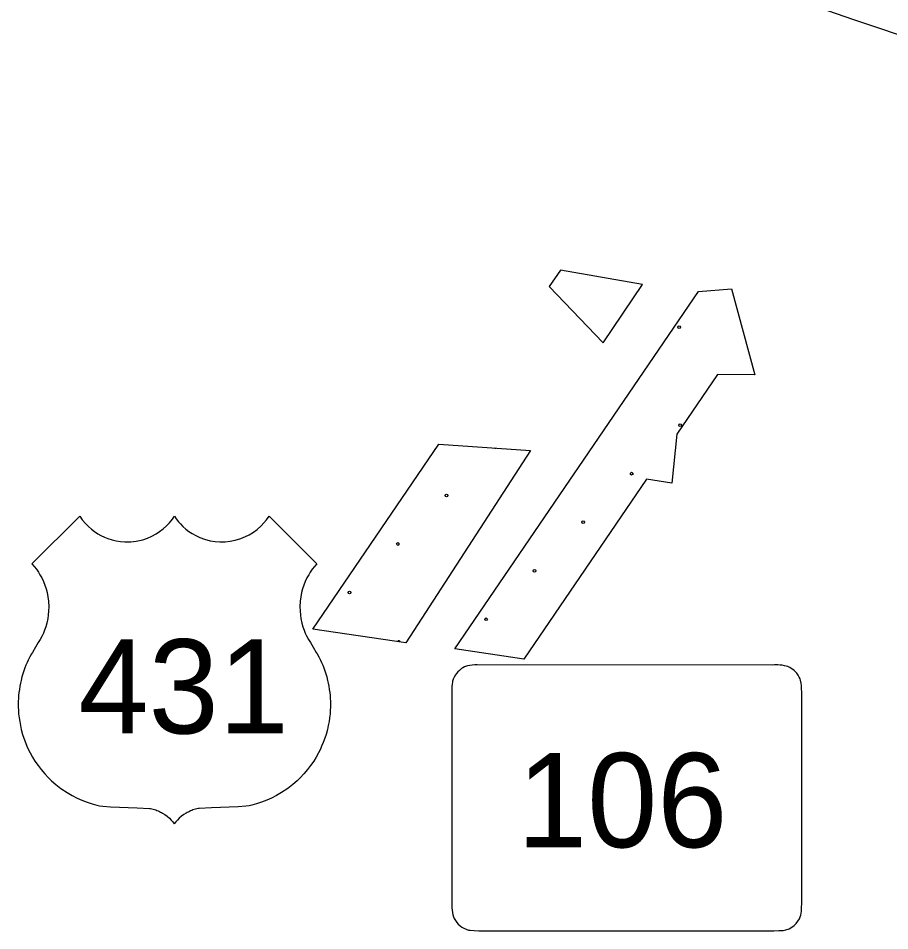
# Model space of a CAD drawing. Extents: x 1612280 to 1883141, y 560852 to 780851.
# Drawn here: x 1710296 to 1713714, y 621879 to 625458 of the extents above; entities that cross this region are included whole.
import ezdxf

# ---------------------------------------------------------------- set-up
doc = ezdxf.new("R2010")
doc.units = 0
for name, color, linetype in [('DESIGN - EROSION CONTROL - Devices', 7, 'Continuous'), ('DESIGN - ROW - Slope Lines', 7, 'Continuous'), ('DESIGN - SCRATCH - User 1', 7, 'Continuous'), ('SURVEY - DRAINAGE - Bridge Deck with Text', 7, 'Continuous')]:
    doc.layers.add(name, color=color, linetype=linetype)

msp = doc.modelspace()

# ---------------------------------------------------------------- linework, layer by layer
at = {"layer": 'DESIGN - EROSION CONTROL - Devices'}
for centre in [(1712888.8, 624246.8), (1712888.8, 624246.8), (1712892.5, 623862.2), (1712892.5, 623862.2), (1712702.1, 623671.8), (1712702.1, 623671.8), (1711975.9, 623586.3), (1711975.9, 623586.3), (1712511.7, 623481.4), (1712511.7, 623481.4), (1711785.5, 623395.9), (1711785.5, 623395.9), (1712321.3, 623291), (1712321.3, 623291), (1711595.1, 623205.5), (1711595.1, 623205.5), (1712130.9, 623100.6), (1712130.9, 623100.6)]:
    msp.add_circle(centre, 5.28, dxfattribs=at)
for centre, start, end in [((1712166.3, 623776.7), 226.9306, 305.1717), ((1711789.2, 623011.3), 356.6323, 166.4726)]:
    msp.add_arc(centre, 5.28, start, end, dxfattribs=at)
at = {"layer": 'DESIGN - ROW - Slope Lines'}
msp.add_line((1711996.3, 622820.2), (1711996.3, 621988.4), dxfattribs=at)
msp.add_line((1711996.3, 622820.2), (1711996.3, 621988.4), dxfattribs=at)
for points in [[(1713369.2, 622809.7), (1713369, 622817.5), (1713368.9, 622825.6), (1713367.8, 622840.2), (1713366.5, 622850.6), (1713364.7, 622861.4), (1713362.7, 622867.4), (1713359.5, 622874), (1713355.1, 622881.5), (1713349.7, 622888.9), (1713345, 622894.3), (1713339.1, 622899.9), (1713334.4, 622903.7), (1713328, 622908.2), (1713323, 622911.1), (1713314.6, 622915.1), (1713308.5, 622917.3), (1713301.4, 622918.7), (1713292.1, 622920.1), (1713284, 622920.9), (1713275.3, 622921.4), (1713263, 622921.6), (1713253.5, 622920.9), (1712096.3, 622921.6), (1712086.9, 622921.6), (1712076.6, 622920.9), (1712067.4, 622919.7), (1712058.4, 622918.1), (1712054.1, 622916.8), (1712046.9, 622913.7), (1712040.4, 622910.3), (1712035.2, 622907.1), (1712026.3, 622900.2), (1712020.2, 622894.4), (1712015, 622888.6), (1712011.1, 622883.3), (1712005.4, 622873.7), (1712002, 622866.3), (1712000.1, 622861.2), (1711999.4, 622857.4), (1711998.9, 622854), (1711998, 622846.8), (1711996.9, 622837.5), (1711996.5, 622829.6), (1711996.3, 622822.9), (1711996.3, 622804.9)], [(1713369.2, 622809.7), (1713369, 622817.5), (1713368.9, 622825.6), (1713367.8, 622840.2), (1713366.5, 622850.6), (1713364.7, 622861.4), (1713362.7, 622867.4), (1713359.5, 622874), (1713355.1, 622881.5), (1713349.7, 622888.9), (1713345, 622894.3), (1713339.1, 622899.9), (1713334.4, 622903.7), (1713328, 622908.2), (1713323, 622911.1), (1713314.6, 622915.1), (1713308.5, 622917.3), (1713301.4, 622918.7), (1713292.1, 622920.1), (1713284, 622920.9), (1713275.3, 622921.4), (1713263, 622921.6), (1713253.5, 622920.9), (1712096.3, 622921.6), (1712086.9, 622921.6), (1712076.6, 622920.9), (1712067.4, 622919.7), (1712058.4, 622918.1), (1712054.1, 622916.8), (1712046.9, 622913.7), (1712040.4, 622910.3), (1712035.2, 622907.1), (1712026.3, 622900.2), (1712020.2, 622894.4), (1712015, 622888.6), (1712011.1, 622883.3), (1712005.4, 622873.7), (1712002, 622866.3), (1712000.1, 622861.2), (1711999.4, 622857.4), (1711998.9, 622854), (1711998, 622846.8), (1711996.9, 622837.5), (1711996.5, 622829.6), (1711996.3, 622822.9), (1711996.3, 622804.9)], [(1713259.3, 621879.1), (1713279.9, 621879.4), (1713297, 621879.6), (1713307.2, 621882.1), (1713319.5, 621886.9), (1713330.6, 621893.3), (1713339.6, 621900.1), (1713347.7, 621908.1), (1713353.9, 621916.1), (1713359.9, 621925.9), (1713363.5, 621933.6), (1713366.1, 621940.7), (1713367.6, 621948.2), (1713368.4, 621956.5), (1713368.7, 621966.5), (1713369.2, 621989.8), (1713369.2, 622809.7)], [(1713259.3, 621879.1), (1713279.9, 621879.4), (1713297, 621879.6), (1713307.2, 621882.1), (1713319.5, 621886.9), (1713330.6, 621893.3), (1713339.6, 621900.1), (1713347.7, 621908.1), (1713353.9, 621916.1), (1713359.9, 621925.9), (1713363.5, 621933.6), (1713366.1, 621940.7), (1713367.6, 621948.2), (1713368.4, 621956.5), (1713368.7, 621966.5), (1713369.2, 621989.8), (1713369.2, 622809.7)], [(1711996.3, 621988.4), (1711996.4, 621979.4), (1711997, 621969.2), (1711997.8, 621959.8), (1711998.9, 621950.6), (1712000.3, 621941.3), (1712003, 621933.7), (1712006.5, 621926.5), (1712011, 621919), (1712016.4, 621911.7), (1712022, 621905.5), (1712029.2, 621898.9), (1712036.2, 621893.7), (1712044.2, 621889), (1712052.8, 621885), (1712061.7, 621881.9), (1712069, 621881), (1712083.9, 621879.7), (1712102.7, 621879), (1713259.3, 621879.1)], [(1711996.3, 621988.4), (1711996.4, 621979.4), (1711997, 621969.2), (1711997.8, 621959.8), (1711998.9, 621950.6), (1712000.3, 621941.3), (1712003, 621933.7), (1712006.5, 621926.5), (1712011, 621919), (1712016.4, 621911.7), (1712022, 621905.5), (1712029.2, 621898.9), (1712036.2, 621893.7), (1712044.2, 621889), (1712052.8, 621885), (1712061.7, 621881.9), (1712069, 621881), (1712083.9, 621879.7), (1712102.7, 621879), (1713259.3, 621879.1)]]:
    msp.add_lwpolyline(points, dxfattribs=at)
at = {"layer": 'DESIGN - SCRATCH - User 1'}
for points in [[(1713573.2, 625451.4), (1712973.7, 625661.3), (1712094, 625973.3)], [(1713573.2, 625451.4), (1712973.7, 625661.3), (1712094, 625973.3)], [(1716206.8, 624740.1), (1715273.3, 624946.3), (1714579.1, 625135.7), (1714107.7, 625273.1), (1713573.2, 625451.4)], [(1716206.8, 624740.1), (1715273.3, 624946.3), (1714579.1, 625135.7), (1714107.7, 625273.1), (1713573.2, 625451.4)], [(1712744.9, 624414), (1712422.8, 624469.7), (1712378, 624406.1)], [(1712744.9, 624414), (1712422.8, 624469.7), (1712378, 624406.1)], [(1712590, 624184.5), (1712744.9, 624414)], [(1712590, 624184.5), (1712744.9, 624414)], [(1712008.5, 622984.5), (1712964, 624386.2), (1713093.8, 624396.2)], [(1712008.5, 622984.5), (1712964, 624386.2), (1713093.8, 624396.2)], [(1712378, 624406.1), (1712590, 624184.5)], [(1712378, 624406.1), (1712590, 624184.5)], [(1713093.8, 624396.2), (1713184.9, 624060)], [(1713093.8, 624396.2), (1713184.9, 624060)], [(1713038.6, 624060.6), (1712879.1, 623826.2)], [(1713038.6, 624060.6), (1712879.1, 623826.2)], [(1713184.9, 624060), (1713038.6, 624060.6)], [(1713184.9, 624060), (1713038.6, 624060.6)], [(1712879.1, 623826.2), (1712860, 623635)], [(1712879.1, 623826.2), (1712860, 623635)], [(1711451.8, 623061.9), (1711945.8, 623787.8), (1712305.1, 623763)], [(1711451.8, 623061.9), (1711945.8, 623787.8), (1712305.1, 623763)], [(1712305.1, 623763), (1711816.5, 623007.8)], [(1712305.1, 623763), (1711816.5, 623007.8)], [(1712759.7, 623650.8), (1712279, 622944.3)], [(1712759.7, 623650.8), (1712279, 622944.3)], [(1712860, 623635), (1712759.7, 623650.8)], [(1712860, 623635), (1712759.7, 623650.8)], [(1711816.5, 623007.8), (1711451.8, 623061.9)], [(1711816.5, 623007.8), (1711451.8, 623061.9)], [(1712279, 622944.3), (1712008.5, 622984.5)], [(1712279, 622944.3), (1712008.5, 622984.5)]]:
    msp.add_lwpolyline(points, dxfattribs=at)
at = {"layer": 'SURVEY - DRAINAGE - Bridge Deck with Text'}
for points in [[(1710350, 623318.2), (1710537.5, 623504.6), (1710547.3, 623490.8), (1710559.6, 623476.1), (1710571.6, 623463.9), (1710582.8, 623454.1), (1710595.2, 623444.7), (1710608.1, 623436.3), (1710620.5, 623429.3), (1710635, 623422.3), (1710648.1, 623417.1), (1710664.5, 623412), (1710680.1, 623408.3), (1710696.6, 623405.7), (1710714.3, 623404.3), (1710722.3, 623404.1), (1710730.4, 623404.2), (1710738.3, 623404.6), (1710748.4, 623405.5), (1710758.8, 623407), (1710772.2, 623409.6), (1710784.7, 623412.8), (1710802.9, 623418.9), (1710820.1, 623426.5), (1710836.6, 623435.4), (1710850.5, 623444.4), (1710864.3, 623454.9), (1710877.6, 623466.8), (1710889.6, 623479.5), (1710900.8, 623493.4), (1710908.7, 623504.6), (1710915.5, 623494.7), (1710924.3, 623483.5), (1710932.3, 623474.5), (1710941.5, 623465.1), (1710953.2, 623454.7), (1710965.7, 623445.2), (1710978.8, 623436.6), (1710992.4, 623428.9), (1711008.4, 623421.4), (1711027, 623414.5), (1711048.3, 623408.9), (1711069.1, 623405.5), (1711087.3, 623404.2), (1711107.1, 623404.4), (1711127.3, 623406.5), (1711147.5, 623410.6), (1711169.8, 623417.4), (1711187.5, 623424.7), (1711202.1, 623432.1), (1711219.1, 623442.6), (1711233.3, 623453.2), (1711249.1, 623467.2), (1711259.9, 623478.5), (1711269.7, 623490.4), (1711279.8, 623504.6), (1711466.6, 623318.2)], [(1710350, 623318.2), (1710537.5, 623504.6), (1710547.3, 623490.8), (1710559.6, 623476.1), (1710571.6, 623463.9), (1710582.8, 623454.1), (1710595.2, 623444.7), (1710608.1, 623436.3), (1710620.5, 623429.3), (1710635, 623422.3), (1710648.1, 623417.1), (1710664.5, 623412), (1710680.1, 623408.3), (1710696.6, 623405.7), (1710714.3, 623404.3), (1710722.3, 623404.1), (1710730.4, 623404.2), (1710738.3, 623404.6), (1710748.4, 623405.5), (1710758.8, 623407), (1710772.2, 623409.6), (1710784.7, 623412.8), (1710802.9, 623418.9), (1710820.1, 623426.5), (1710836.6, 623435.4), (1710850.5, 623444.4), (1710864.3, 623454.9), (1710877.6, 623466.8), (1710889.6, 623479.5), (1710900.8, 623493.4), (1710908.7, 623504.6), (1710915.5, 623494.7), (1710924.3, 623483.5), (1710932.3, 623474.5), (1710941.5, 623465.1), (1710953.2, 623454.7), (1710965.7, 623445.2), (1710978.8, 623436.6), (1710992.4, 623428.9), (1711008.4, 623421.4), (1711027, 623414.5), (1711048.3, 623408.9), (1711069.1, 623405.5), (1711087.3, 623404.2), (1711107.1, 623404.4), (1711127.3, 623406.5), (1711147.5, 623410.6), (1711169.8, 623417.4), (1711187.5, 623424.7), (1711202.1, 623432.1), (1711219.1, 623442.6), (1711233.3, 623453.2), (1711249.1, 623467.2), (1711259.9, 623478.5), (1711269.7, 623490.4), (1711279.8, 623504.6), (1711466.6, 623318.2)], [(1710350, 623318.2), (1710359.2, 623307.5), (1710367.4, 623296.8), (1710375, 623285.7), (1710381.3, 623275.4), (1710388.1, 623263), (1710394.6, 623249.1), (1710400.2, 623235), (1710405.4, 623219.6), (1710409.2, 623205.1), (1710412.4, 623189.2), (1710414.6, 623171.4), (1710415.7, 623149.8), (1710415.4, 623133.3), (1710414, 623117.4), (1710411.9, 623103.4), (1710408, 623085.2), (1710404.1, 623071.4), (1710399.6, 623058.2), (1710394.6, 623046.1), (1710389.8, 623035.7), (1710382.1, 623022), (1710374.8, 623009.4), (1710364.4, 622991.8), (1710351.5, 622970.7), (1710347.8, 622964.7), (1710341.9, 622953.7), (1710335.3, 622940.5), (1710331.1, 622931.4), (1710326.3, 622920.1), (1710322.2, 622909.8), (1710318.3, 622898.8), (1710314.5, 622887.1), (1710310.8, 622874.5), (1710307.3, 622861.1), (1710304.8, 622849.9), (1710302.4, 622837.8), (1710300.5, 622825.9), (1710298.8, 622813.2), (1710297.6, 622801.6), (1710296.8, 622790), (1710296.3, 622779.2), (1710296.1, 622768), (1710296.2, 622755.6), (1710296.7, 622744), (1710297.7, 622729.5), (1710299.4, 622714.4), (1710301.7, 622699.1), (1710304.4, 622684.4), (1710308.1, 622668.1), (1710313.4, 622649), (1710318, 622634.4), (1710324.5, 622616.8), (1710330.4, 622603.2), (1710335.5, 622591.6), (1710342.8, 622576.9), (1710352.6, 622559.4), (1710361.7, 622544.7), (1710373.7, 622527.2), (1710386.2, 622510.9), (1710400, 622494.6), (1710414.5, 622479.3), (1710427, 622467.3), (1710443.9, 622452.6), (1710463.6, 622437.2), (1710487.8, 622420.9), (1710508.1, 622409.1), (1710527.5, 622399.2), (1710545.6, 622391.1), (1710566.4, 622383), (1710585.6, 622376.7), (1710605, 622371.4), (1710614.9, 622369.1), (1710627.5, 622367.4), (1710657.6, 622364.8), (1710763.2, 622361.5), (1710810.9, 622359), (1710815.4, 622358.5), (1710820.3, 622357.4), (1710825.4, 622356.1), (1710830.4, 622354.6), (1710835.2, 622353), (1710839.8, 622351.3), (1710845.1, 622349.2), (1710849.5, 622347.2), (1710854.6, 622344.7), (1710858.5, 622342.7), (1710862.5, 622340.4), (1710871.1, 622335), (1710880.2, 622328.3), (1710888.8, 622320.9), (1710896.4, 622313.4), (1710902.8, 622306), (1710908.3, 622297.8)], [(1710350, 623318.2), (1710359.2, 623307.5), (1710367.4, 623296.8), (1710375, 623285.7), (1710381.3, 623275.4), (1710388.1, 623263), (1710394.6, 623249.1), (1710400.2, 623235), (1710405.4, 623219.6), (1710409.2, 623205.1), (1710412.4, 623189.2), (1710414.6, 623171.4), (1710415.7, 623149.8), (1710415.4, 623133.3), (1710414, 623117.4), (1710411.9, 623103.4), (1710408, 623085.2), (1710404.1, 623071.4), (1710399.6, 623058.2), (1710394.6, 623046.1), (1710389.8, 623035.7), (1710382.1, 623022), (1710374.8, 623009.4), (1710364.4, 622991.8), (1710351.5, 622970.7), (1710347.8, 622964.7), (1710341.9, 622953.7), (1710335.3, 622940.5), (1710331.1, 622931.4), (1710326.3, 622920.1), (1710322.2, 622909.8), (1710318.3, 622898.8), (1710314.5, 622887.1), (1710310.8, 622874.5), (1710307.3, 622861.1), (1710304.8, 622849.9), (1710302.4, 622837.8), (1710300.5, 622825.9), (1710298.8, 622813.2), (1710297.6, 622801.6), (1710296.8, 622790), (1710296.3, 622779.2), (1710296.1, 622768), (1710296.2, 622755.6), (1710296.7, 622744), (1710297.7, 622729.5), (1710299.4, 622714.4), (1710301.7, 622699.1), (1710304.4, 622684.4), (1710308.1, 622668.1), (1710313.4, 622649), (1710318, 622634.4), (1710324.5, 622616.8), (1710330.4, 622603.2), (1710335.5, 622591.6), (1710342.8, 622576.9), (1710352.6, 622559.4), (1710361.7, 622544.7), (1710373.7, 622527.2), (1710386.2, 622510.9), (1710400, 622494.6), (1710414.5, 622479.3), (1710427, 622467.3), (1710443.9, 622452.6), (1710463.6, 622437.2), (1710487.8, 622420.9), (1710508.1, 622409.1), (1710527.5, 622399.2), (1710545.6, 622391.1), (1710566.4, 622383), (1710585.6, 622376.7), (1710605, 622371.4), (1710614.9, 622369.1), (1710627.5, 622367.4), (1710657.6, 622364.8), (1710763.2, 622361.5), (1710810.9, 622359), (1710815.4, 622358.5), (1710820.3, 622357.4), (1710825.4, 622356.1), (1710830.4, 622354.6), (1710835.2, 622353), (1710839.8, 622351.3), (1710845.1, 622349.2), (1710849.5, 622347.2), (1710854.6, 622344.7), (1710858.5, 622342.7), (1710862.5, 622340.4), (1710871.1, 622335), (1710880.2, 622328.3), (1710888.8, 622320.9), (1710896.4, 622313.4), (1710902.8, 622306), (1710908.3, 622297.8)], [(1711466.6, 623318.2), (1711457.5, 623307.6), (1711449.3, 623296.9), (1711441.7, 623285.7), (1711435.4, 623275.4), (1711428.5, 623263), (1711422, 623249.1), (1711416.4, 623235), (1711411.3, 623219.6), (1711407.5, 623205.2), (1711404.3, 623189.2), (1711402, 623171.5), (1711400.9, 623149.8), (1711401.3, 623133.4), (1711402.7, 623117.4), (1711404.7, 623103.4), (1711408.7, 623085.2), (1711412.6, 623071.4), (1711417.1, 623058.3), (1711422, 623046.2), (1711426.8, 623035.8), (1711434.6, 623022), (1711441.8, 623009.5), (1711452.3, 622991.8), (1711465.2, 622970.7), (1711468.8, 622964.8), (1711474.8, 622953.7), (1711481.4, 622940.6), (1711485.5, 622931.4), (1711490.3, 622920.1), (1711494.4, 622909.8), (1711498.3, 622898.8), (1711502.2, 622887.1), (1711505.9, 622874.5), (1711509.4, 622861.1), (1711511.9, 622849.9), (1711514.2, 622837.9), (1711516.2, 622825.9), (1711517.9, 622813.2), (1711519.1, 622801.6), (1711519.9, 622790.1), (1711520.4, 622779.2), (1711520.6, 622768.1), (1711520.4, 622755.6), (1711520, 622744), (1711518.9, 622729.5), (1711517.3, 622714.4), (1711515, 622699.1), (1711512.2, 622684.4), (1711508.6, 622668.1), (1711503.3, 622649), (1711498.6, 622634.4), (1711492.2, 622616.8), (1711486.2, 622603.2), (1711481.2, 622591.6), (1711473.9, 622577), (1711464.1, 622559.5), (1711455, 622544.8), (1711443, 622527.3), (1711430.4, 622510.9), (1711416.6, 622494.6), (1711402.2, 622479.3), (1711389.7, 622467.3), (1711372.8, 622452.6), (1711353.1, 622437.2), (1711328.9, 622420.9), (1711308.6, 622409.2), (1711289.2, 622399.2), (1711271.1, 622391.1), (1711250.3, 622383.1), (1711231, 622376.7), (1711211.7, 622371.4), (1711201.8, 622369.1), (1711189.2, 622367.4), (1711159.1, 622364.8), (1711053.5, 622361.5), (1711005.8, 622359), (1711001.3, 622358.5), (1710996.4, 622357.4), (1710991.3, 622356.1), (1710986.3, 622354.6), (1710981.5, 622353), (1710976.9, 622351.3), (1710971.6, 622349.2), (1710967.2, 622347.2), (1710962.1, 622344.7), (1710958.2, 622342.7), (1710954.1, 622340.4), (1710945.6, 622335), (1710936.5, 622328.3), (1710927.9, 622320.9), (1710920.3, 622313.4), (1710913.9, 622306), (1710908.3, 622297.8)], [(1711466.6, 623318.2), (1711457.5, 623307.6), (1711449.3, 623296.9), (1711441.7, 623285.7), (1711435.4, 623275.4), (1711428.5, 623263), (1711422, 623249.1), (1711416.4, 623235), (1711411.3, 623219.6), (1711407.5, 623205.2), (1711404.3, 623189.2), (1711402, 623171.5), (1711400.9, 623149.8), (1711401.3, 623133.4), (1711402.7, 623117.4), (1711404.7, 623103.4), (1711408.7, 623085.2), (1711412.6, 623071.4), (1711417.1, 623058.3), (1711422, 623046.2), (1711426.8, 623035.8), (1711434.6, 623022), (1711441.8, 623009.5), (1711452.3, 622991.8), (1711465.2, 622970.7), (1711468.8, 622964.8), (1711474.8, 622953.7), (1711481.4, 622940.6), (1711485.5, 622931.4), (1711490.3, 622920.1), (1711494.4, 622909.8), (1711498.3, 622898.8), (1711502.2, 622887.1), (1711505.9, 622874.5), (1711509.4, 622861.1), (1711511.9, 622849.9), (1711514.2, 622837.9), (1711516.2, 622825.9), (1711517.9, 622813.2), (1711519.1, 622801.6), (1711519.9, 622790.1), (1711520.4, 622779.2), (1711520.6, 622768.1), (1711520.4, 622755.6), (1711520, 622744), (1711518.9, 622729.5), (1711517.3, 622714.4), (1711515, 622699.1), (1711512.2, 622684.4), (1711508.6, 622668.1), (1711503.3, 622649), (1711498.6, 622634.4), (1711492.2, 622616.8), (1711486.2, 622603.2), (1711481.2, 622591.6), (1711473.9, 622577), (1711464.1, 622559.5), (1711455, 622544.8), (1711443, 622527.3), (1711430.4, 622510.9), (1711416.6, 622494.6), (1711402.2, 622479.3), (1711389.7, 622467.3), (1711372.8, 622452.6), (1711353.1, 622437.2), (1711328.9, 622420.9), (1711308.6, 622409.2), (1711289.2, 622399.2), (1711271.1, 622391.1), (1711250.3, 622383.1), (1711231, 622376.7), (1711211.7, 622371.4), (1711201.8, 622369.1), (1711189.2, 622367.4), (1711159.1, 622364.8), (1711053.5, 622361.5), (1711005.8, 622359), (1711001.3, 622358.5), (1710996.4, 622357.4), (1710991.3, 622356.1), (1710986.3, 622354.6), (1710981.5, 622353), (1710976.9, 622351.3), (1710971.6, 622349.2), (1710967.2, 622347.2), (1710962.1, 622344.7), (1710958.2, 622342.7), (1710954.1, 622340.4), (1710945.6, 622335), (1710936.5, 622328.3), (1710927.9, 622320.9), (1710920.3, 622313.4), (1710913.9, 622306), (1710908.3, 622297.8)]]:
    msp.add_lwpolyline(points, dxfattribs=at)

# ---------------------------------------------------------------- texts
at = {"layer": 'DESIGN - ROW - Slope Lines'}
msp.add_text('106', height=369.61, rotation=0.0011, dxfattribs=at).set_placement((1712252.9, 622206.4))
msp.add_text('106', height=369.61, rotation=0.0011, dxfattribs=at).set_placement((1712252.9, 622206.4))
at = {"layer": 'SURVEY - DRAINAGE - Bridge Deck with Text'}
msp.add_text('431', height=369.6, rotation=0.0013, dxfattribs=at).set_placement((1710532.6, 622652.7))
msp.add_text('431', height=369.6, rotation=0.0013, dxfattribs=at).set_placement((1710532.6, 622652.7))

doc.saveas('drawing.dxf')
